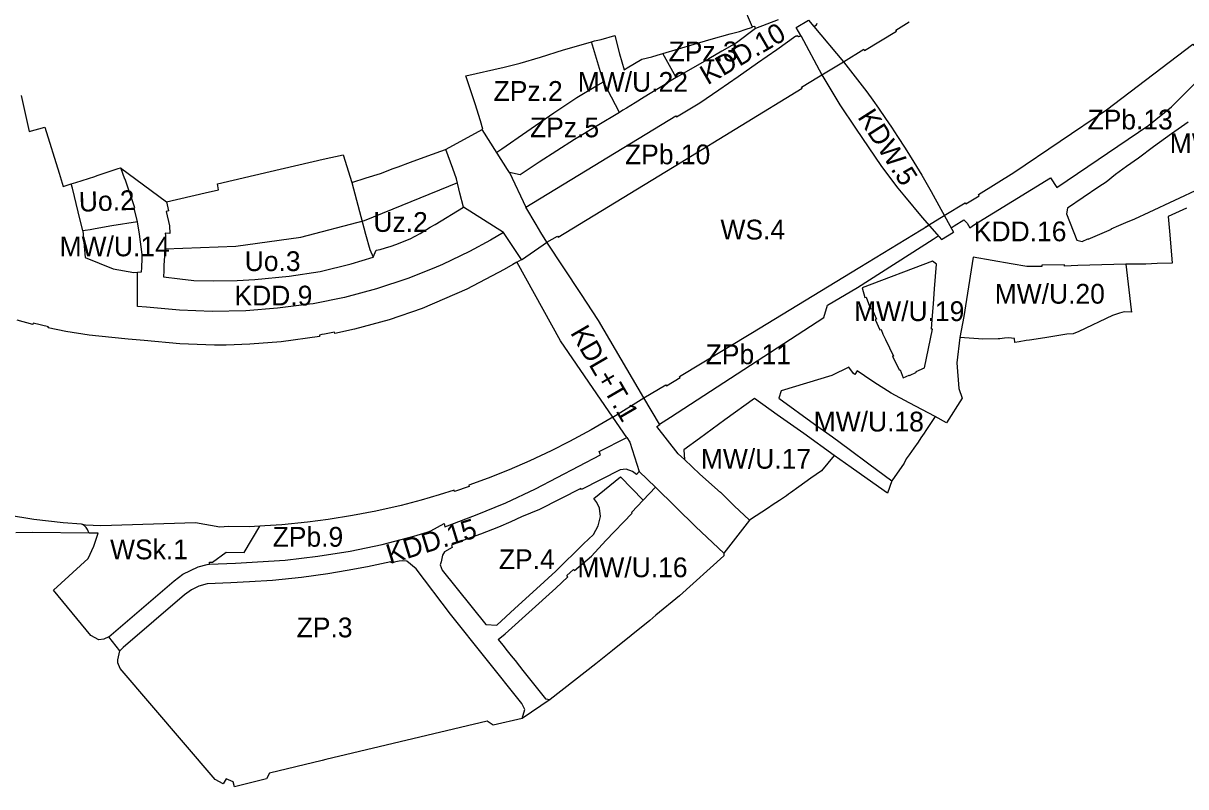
# Model space of a CAD drawing. Extents: x 7421697 to 7426767, y 5545731 to 5547485.
# Drawn here: x 7424103 to 7424808, y 5545731 to 5546195 of the extents above; entities that cross this region are included whole.
import ezdxf

# ---------------------------------------------------------------- set-up
doc = ezdxf.new("R2010")
doc.units = 0
for name, color, linetype in [('LIN_Linia Zabudowy Nieprzekraczalna', 7, 'Continuous'), ('LIN_linie rozgraniczające terenu WS', 7, 'Continuous'), ('LIN_linie_rozgraniczajace', 7, 'Continuous'), ('TXT_oznaczenia_przeznaczen', 7, 'Continuous')]:
    doc.layers.add(name, color=color, linetype=linetype)

msp = doc.modelspace()

# ---------------------------------------------------------------- linework, layer by layer
at = {"layer": 'LIN_Linia Zabudowy Nieprzekraczalna'}
msp.add_lwpolyline([(7424188.67, 5546057.57), (7424231.56, 5546059.31), (7424271.15, 5546064.63), (7424309.6, 5546074.83), (7424366.27, 5546097.92)], dxfattribs=at)
at = {"layer": 'LIN_linie rozgraniczające terenu WS'}
for p, q in [((7424587.09, 5546163.3), (7424600.39, 5546171.17)), ((7424649.85, 5546070.74), (7424663.46, 5546079.04)), ((7424404.94, 5546051.05), (7424420.79, 5546061.97)), ((7424460.37, 5545955.49), (7424479.27, 5545967.2))]:
    msp.add_line(p, q, dxfattribs=at)
at = {"layer": 'LIN_linie_rozgraniczajace'}
for p, q in [((7424613.11, 5546178.03), (7424632.48, 5546189.8)), ((7424632.03, 5546190.43), (7424640.26, 5546195.44)), ((7424632.48, 5546189.8), (7424632.03, 5546190.43)), ((7424600.39, 5546171.17), (7424612.71, 5546178.75)), ((7424612.71, 5546178.75), (7424613.11, 5546178.03)), ((7424574.84, 5546155.74), (7424585.09, 5546162.09)), ((7424585.09, 5546162.09), (7424587.09, 5546163.3)), ((7424427.2, 5546064.7), (7424501.23, 5546109.89)), ((7424420.39, 5546061.74), (7424426.78, 5546065.34)), ((7424426.78, 5546065.34), (7424427.2, 5546064.7)), ((7424503.4, 5545935.69), (7424503.87, 5545929.68))]:
    msp.add_line(p, q, dxfattribs=at)
for points in [[(7424661.5, 5546077.85), (7424674.13, 5546085.55), (7424674.6, 5546084.85), (7424682.6, 5546089.82), (7424682.16, 5546090.62), (7424703.77, 5546103.94), (7424759.9, 5546141.92), (7424812.22, 5546181.85), (7424812.78, 5546181.29), (7424819.99, 5546187.21), (7424819.56, 5546187.81), (7424862.07, 5546222.28), (7424940.6, 5546285.37), (7424941.01, 5546284.88), (7424947.89, 5546290.38), (7424947.41, 5546291.07), (7424989.15, 5546324.66), (7425042.17, 5546367.38), (7425042.68, 5546366.91), (7425050.01, 5546372.94), (7425049.68, 5546373.37), (7425057.27, 5546379.65)], [(7424726.02, 5546100.65), (7424729.7, 5546094.76), (7424785.69, 5546132.59), (7424799.27, 5546143.76), (7424814.44, 5546158.92), (7424817.02, 5546156.64), (7424824.01, 5546164.62), (7424825.31, 5546163.3), (7424847.73, 5546174.18), (7424880.46, 5546189.25), (7424887.59, 5546192.02), (7424920.27, 5546204.59), (7424932.07, 5546209.24), (7424938.37, 5546211.81), (7424940.05, 5546212.41), (7424965.34, 5546222.37)], [(7424101.33, 5546150.7), (7424106.15, 5546128.94), (7424115.62, 5546131.45), (7424124.43, 5546103.47), (7424126.76, 5546095.42), (7424131.78, 5546097.02), (7424134.43, 5546097.87), (7424146.06, 5546101.58), (7424147.53, 5546102.08), (7424160.13, 5546106.33), (7424161.71, 5546106.86), (7424189.62, 5546086.1), (7424212.98, 5546091.55), (7424221.18, 5546093.49), (7424220.42, 5546097.17), (7424252.51, 5546104.62), (7424284.6, 5546112.07), (7424296.8, 5546114.75), (7424301.95, 5546097.81), (7424310.65, 5546100.63), (7424319.35, 5546103.44), (7424327.17, 5546106.31), (7424330.13, 5546107.4), (7424337.57, 5546110.13), (7424348.21, 5546113.98), (7424358.85, 5546117.82), (7424381.51, 5546130.31), (7424380.05, 5546135.25), (7424376.88, 5546145.57), (7424371.09, 5546162.62), (7424394.47, 5546167.81), (7424404.05, 5546170.39), (7424416.4, 5546174.05), (7424430.44, 5546178.37), (7424435.59, 5546179.86), (7424447.5, 5546183.3), (7424449.33, 5546183.82), (7424453.36, 5546184.73), (7424461.49, 5546187.01), (7424464.34, 5546175.96), (7424467.22, 5546166.19), (7424469.05, 5546167.46), (7424477.89, 5546172.7), (7424484.1, 5546174.23), (7424487.3, 5546175.18), (7424490.61, 5546176.16), (7424509.81, 5546181.88), (7424520.1, 5546184.81), (7424531.63, 5546188.05), (7424537.19, 5546189.56), (7424540.62, 5546190.71), (7424545.19, 5546192.12), (7424539.23, 5546206)], [(7424560.75, 5546196.68), (7424546.86, 5546191.31), (7424535.36, 5546182.66), (7424526.55, 5546177.69), (7424518.53, 5546173.04), (7424510.5, 5546168.38), (7424498.82, 5546161.61), (7424498.72, 5546161.55), (7424495.69, 5546159.85), (7424495.77, 5546159.71), (7424492.03, 5546157.43), (7424492.09, 5546157.32), (7424483, 5546151.84), (7424482.93, 5546151.95), (7424479.38, 5546149.76), (7424473.98, 5546146.34), (7424468.58, 5546142.93), (7424466.49, 5546141.69), (7424464.4, 5546140.44), (7424450.77, 5546132.22), (7424437.14, 5546124.01), (7424415.75, 5546110.28), (7424404.24, 5546102.58), (7424397.72, 5546103.87), (7424407.56, 5546082.85), (7424453.09, 5546110.59), (7424498.62, 5546138.32), (7424498.99, 5546137.75), (7424513.17, 5546146.25), (7424524.76, 5546154.15), (7424536.49, 5546162.32), (7424548.23, 5546170.49), (7424548.23, 5546170.49), (7424559.8, 5546178.7), (7424571.38, 5546186.91), (7424571.64, 5546186.52), (7424572.26, 5546187.02), (7424573.11, 5546186.47), (7424573.79, 5546186.66), (7424574.46, 5546187.12), (7424571.69, 5546192.01), (7424579.06, 5546196.33), (7424582.31, 5546192.49), (7424583.87, 5546193.55), (7424584.26, 5546194.6)], [(7424546.86, 5546191.31), (7424546.44, 5546192.52), (7424545.11, 5546192.32)], [(7424582.31, 5546192.49), (7424600.39, 5546171.17), (7424614.59, 5546152.9), (7424618.11, 5546147.95), (7424621.55, 5546142.92), (7424625.89, 5546136.74), (7424629.48, 5546131.46), (7424633.14, 5546125.85), (7424637.71, 5546118.81), (7424642.99, 5546110.25), (7424647.79, 5546102.29), (7424653.46, 5546092.47), (7424659.42, 5546081.63), (7424667.08, 5546067.7)], [(7424464.4, 5546140.44), (7424454.67, 5546158.92), (7424447.5, 5546183.3)], [(7424574.46, 5546187.12), (7424587.09, 5546163.3), (7424598.19, 5546145.08), (7424607.56, 5546130.84), (7424623.42, 5546107.69), (7424633.38, 5546094.51), (7424637.32, 5546089.56), (7424648.09, 5546076.64), (7424656.96, 5546066.46), (7424659.87, 5546063.33)], [(7424498.82, 5546161.61), (7424490.61, 5546176.16)], [(7424389.92, 5546116.2), (7424393.09, 5546118.28), (7424408.21, 5546128.87), (7424424.64, 5546140.14), (7424438.61, 5546149.43), (7424450.1, 5546156.27), (7424454.67, 5546158.92)], [(7424501.23, 5546109.89), (7424575.26, 5546155.09), (7424574.84, 5546155.74)], [(7424809.47, 5546134.53), (7424799.3, 5546127.52), (7424788.51, 5546119.6), (7424779.38, 5546112.7), (7424772.1, 5546107.6), (7424765.39, 5546102.68), (7424759.79, 5546098.14), (7424755.32, 5546095.28), (7424736.16, 5546082.26), (7424735.65, 5546078.9), (7424741.94, 5546062.85), (7424745.12, 5546062.06), (7424748.6, 5546063.68), (7424748.73, 5546063.49), (7424762.88, 5546069.6), (7424762.83, 5546069.75), (7424767.43, 5546071.74), (7424771.6, 5546073.58), (7424777.19, 5546075.87), (7424785.77, 5546079.88), (7424848.07, 5546108.93)], [(7424397.72, 5546103.87), (7424396.53, 5546105.75), (7424390.18, 5546115.79), (7424381.06, 5546130.06)], [(7424468.81, 5545943.17), (7424460.37, 5545955.49), (7424428.66, 5546001.79), (7424402.32, 5546049.26), (7424402.17, 5546049.54), (7424404.88, 5546051.15), (7424394, 5546067.56), (7424369.71, 5546082.87), (7424367.58, 5546091.46), (7424365.46, 5546100.04), (7424363.2, 5546106.38), (7424359.08, 5546117.95)], [(7424394, 5546067.56), (7424386.24, 5546062.84), (7424373.35, 5546056.1), (7424357.02, 5546048.04), (7424351.81, 5546045.86), (7424335.93, 5546039.66), (7424316.96, 5546033.33), (7424297.54, 5546028.08), (7424278.49, 5546024.28), (7424276.32, 5546024), (7424256.98, 5546021.52), (7424237.75, 5546020.04), (7424217.21, 5546019.67), (7424197.37, 5546020.37), (7424177.35, 5546022.14), (7424171.91, 5546022.67), (7424171.93, 5546042.54), (7424171.92, 5546043.55), (7424174.4, 5546043.76), (7424174.55, 5546046.09), (7424174.56, 5546047.23), (7424174.7, 5546050.73), (7424174.84, 5546054.23), (7424173.25, 5546066.49), (7424172.02, 5546074.08), (7424170, 5546082.34), (7424170.25, 5546082.45), (7424164.51, 5546099.97), (7424164.26, 5546099.88), (7424161.88, 5546106.74)], [(7424665.61, 5546070.39), (7424667.5, 5546071.6), (7424673.41, 5546075.17), (7424675.34, 5546073.12), (7424676.95, 5546070.29), (7424679.88, 5546072.3), (7424726.02, 5546100.65)], [(7424172.02, 5546074.08), (7424156.37, 5546071.53), (7424146.32, 5546069.79), (7424143.24, 5546069.25), (7424140.16, 5546068.72), (7424138.85, 5546068.51), (7424136, 5546080.17), (7424132.43, 5546094.42), (7424131.78, 5546097.02)], [(7424301.95, 5546097.81), (7424310.36, 5546066.43), (7424312.93, 5546057.28), (7424314.86, 5546052.51)], [(7424189.62, 5546086.1), (7424190.68, 5546080.72), (7424189.3, 5546080.37), (7424191.35, 5546071.66), (7424191.63, 5546066.96), (7424188.82, 5546067.06), (7424188.88, 5546065.7), (7424188.69, 5546062.56), (7424188.5, 5546059.41), (7424188.26, 5546053.44), (7424188.02, 5546047.47), (7424187.84, 5546044.33), (7424187.72, 5546040.61), (7424197.71, 5546039.33), (7424206.07, 5546038.49), (7424218.09, 5546038.15), (7424232.44, 5546038.36), (7424243.16, 5546038.93), (7424263.92, 5546041.02), (7424282.78, 5546043.97), (7424301.52, 5546048.45), (7424314.86, 5546052.51), (7424316.69, 5546056.73), (7424319.14, 5546057.28), (7424322.35, 5546058.15), (7424325.95, 5546059.24), (7424328.75, 5546060.25), (7424337.33, 5546063.71), (7424343.56, 5546066.98), (7424349.63, 5546070.71), (7424352.64, 5546072.47), (7424369.71, 5546082.87)], [(7424808.45, 5546082.3), (7424797.36, 5546077.18), (7424798.26, 5546066.2), (7424799.84, 5546048.89), (7424790.61, 5546048.75), (7424783.79, 5546048.22), (7424771.74, 5546048.37), (7424774.95, 5546020.68), (7424775.08, 5546019.1), (7424770.7, 5546019.31), (7424767.88, 5546018.68), (7424763.65, 5546017.25), (7424743.21, 5546007.47), (7424739.64, 5546006.03), (7424735.8, 5546005.93), (7424729.77, 5546004.85), (7424727.38, 5546004.42), (7424722.6, 5546003.69), (7424713.15, 5546002.25), (7424711.09, 5546001.94), (7424706.97, 5546001.14), (7424704.31, 5546000.74), (7424704.08, 5546003.26), (7424700.39, 5546003.6), (7424698.07, 5546003.35), (7424695.16, 5546003.06), (7424694.13, 5546002.94), (7424684.64, 5546002.85), (7424682.18, 5546003), (7424670.83, 5546003.74), (7424669.2, 5545988.43), (7424670.36, 5545972.81), (7424672.29, 5545966.97), (7424662.89, 5545952.08), (7424655.9, 5545955.88), (7424650.34, 5545947.38), (7424649.26, 5545945.79), (7424647.32, 5545942.84), (7424645.64, 5545940.29), (7424642.98, 5545936.57), (7424640.17, 5545932.63), (7424638.45, 5545930.2), (7424637.11, 5545927.45), (7424629.71, 5545916.81), (7424627.04, 5545909.31), (7424614.75, 5545918.04), (7424605.07, 5545924.98), (7424594.64, 5545932.29), (7424586.92, 5545922.86), (7424580.61, 5545918.49), (7424573.29, 5545913.23), (7424568.1, 5545909.49), (7424567.04, 5545908.71), (7424565.78, 5545907.77), (7424561.48, 5545904.79), (7424557.01, 5545902.06), (7424554.74, 5545900.52), (7424543.33, 5545892.87), (7424527.77, 5545872.97), (7424527.75, 5545871.27), (7424500.88, 5545847.03), (7424486.55, 5545835.35), (7424482.89, 5545832.08), (7424460.15, 5545813.92), (7424450.03, 5545805.7), (7424437.19, 5545795.66), (7424422.38, 5545784.09), (7424405.27, 5545772.63), (7424387.67, 5545768.43), (7424384.02, 5545770.97), (7424286.2, 5545747.59), (7424283.97, 5545747.07), (7424252.14, 5545739.42), (7424250.25, 5545736.03), (7424230.71, 5545731.14), (7424229.96, 5545734.09), (7424225.84, 5545736), (7424223.94, 5545732.91), (7424219.03, 5545735.62), (7424161.47, 5545802.94), (7424159.98, 5545806.34), (7424160.04, 5545808.19), (7424161.26, 5545813.57), (7424154.51, 5545822.14), (7424151.49, 5545820.74), (7424148.46, 5545820.35), (7424143.59, 5545822.91), (7424120.89, 5545850.41), (7424141.94, 5545869.64), (7424145.35, 5545877.24), (7424148.1, 5545884.97), (7424142.71, 5545885.03), (7424108.1, 5545885.42), (7424098.05, 5545885.35)], [(7424543.33, 5545892.87), (7424534.06, 5545901.69), (7424525.72, 5545909.88), (7424525.61, 5545909.77), (7424513.26, 5545920.85), (7424503.87, 5545929.68), (7424500.06, 5545933.27), (7424487.02, 5545949.72), (7424488.87, 5545950.94), (7424488.69, 5545951.24), (7424479.27, 5545967.2), (7424451.6, 5546014.05), (7424440.96, 5546030.46), (7424420.39, 5546061.74), (7424416.7, 5546067.64), (7424413.86, 5546072.38), (7424407.56, 5546082.85)], [(7424479.27, 5545967.2), (7424492.56, 5545975.03), (7424492.98, 5545974.46), (7424501.13, 5545979.5), (7424500.74, 5545980.18), (7424544.18, 5546006.26), (7424610.18, 5546046.57), (7424652.05, 5546072.09)], [(7424138.85, 5546068.51), (7424140.28, 5546052.41), (7424157.13, 5546045.42), (7424169.69, 5546043.36), (7424171.92, 5546043.55)], [(7424488.69, 5545951.24), (7424495.31, 5545955.42), (7424588.36, 5546015.9), (7424590.67, 5546023.47), (7424608.83, 5546034.23), (7424654.75, 5546063.47)], [(7424654.75, 5546063.47), (7424657.88, 5546065.47)], [(7424659.87, 5546063.33), (7424667.08, 5546067.7)], [(7424402.17, 5546049.54), (7424399.7, 5546048.07), (7424394.52, 5546045), (7424371.75, 5546033.08), (7424371.75, 5546033.08), (7424358.21, 5546027.28), (7424344.67, 5546021.47), (7424324.6, 5546014.59), (7424303.65, 5546008.86), (7424291.76, 5546006.2), (7424291.58, 5546007.05), (7424288.49, 5546006.46), (7424285.39, 5546005.88), (7424283.87, 5546005.58), (7424282.35, 5546005.29), (7424282.46, 5546004.47), (7424259.03, 5546001.16), (7424240.06, 5545999.68), (7424225.75, 5545999.2), (7424218.75, 5545999.22), (7424197.59, 5546000.04), (7424176.04, 5546001.89), (7424166.25, 5546002.82), (7424156.46, 5546003.74), (7424142.59, 5546005.26), (7424128.45, 5546007.47), (7424117.7, 5546009.58), (7424117.87, 5546010.38), (7424108.67, 5546012.49), (7424108.51, 5546011.67), (7424098.91, 5546014.37)], [(7424656.76, 5546048.32), (7424654.31, 5546050.13), (7424611.6, 5546033.97)], [(7424771.74, 5546048.37), (7424742.43, 5546047.45), (7424734.42, 5546047.18), (7424734.49, 5546047.85), (7424720.68, 5546047.62), (7424720.68, 5546046.98), (7424711.56, 5546046.85), (7424702.05, 5546048.56), (7424679.01, 5546052.66), (7424674.92, 5546026.78), (7424673.28, 5546016.49), (7424670.83, 5546003.74)], [(7424611.6, 5546033.97), (7424613.32, 5546028.17), (7424614.01, 5546028.29), (7424616.74, 5546021.18), (7424617.51, 5546021.4), (7424620.35, 5546015.02), (7424619.62, 5546014.66), (7424622.47, 5546008.48), (7424623.14, 5546008.63), (7424624.3, 5546005.8), (7424625.79, 5546002.63), (7424630.59, 5545992.57), (7424630.04, 5545992.52), (7424634.16, 5545984.15), (7424634.76, 5545984.22), (7424636.61, 5545979.33), (7424640.25, 5545981.03), (7424640.45, 5545980.73), (7424644.6, 5545982.8), (7424644.47, 5545983.08), (7424649.52, 5545985.48), (7424654.38, 5546008.88), (7424653.77, 5546008.83), (7424654.23, 5546014.78), (7424654.89, 5546024.34), (7424655.46, 5546033.45), (7424656.76, 5546048.32)], [(7424655.9, 5545955.88), (7424640.24, 5545964.19), (7424629.35, 5545969.97), (7424618.76, 5545976.7), (7424613.14, 5545980.49), (7424608.63, 5545983.52), (7424607.14, 5545981.37), (7424606.32, 5545981.93), (7424603.53, 5545985.87), (7424593.18, 5545980.66), (7424562.61, 5545971.41), (7424561.06, 5545966.94), (7424582.82, 5545951.27), (7424593.7, 5545943.45), (7424603.69, 5545936), (7424615.68, 5545927.14), (7424629.71, 5545916.81)], [(7424594.64, 5545932.29), (7424576.25, 5545945.5), (7424560.01, 5545956.92), (7424546.24, 5545966.81), (7424528.35, 5545953.82), (7424512.87, 5545942.58), (7424503.4, 5545935.69)], [(7424460.37, 5545955.49), (7424459.45, 5545954.93), (7424447.25, 5545947.74), (7424434.12, 5545940.6), (7424422.92, 5545934.93), (7424410.02, 5545928.87), (7424397.52, 5545923.49), (7424384.69, 5545918.42), (7424373.03, 5545914.17), (7424373.29, 5545913.38), (7424364.29, 5545910.3), (7424364.03, 5545911.13), (7424354.94, 5545908.27), (7424344.08, 5545905.12), (7424331.92, 5545901.94), (7424316.59, 5545898.41), (7424302.5, 5545895.71), (7424287.65, 5545893.33), (7424275.17, 5545891.68), (7424259.54, 5545890.17), (7424249.23, 5545889.47), (7424246.17, 5545889.26), (7424239.63, 5545888.81), (7424227.08, 5545889.06), (7424221.85, 5545888.66), (7424207.08, 5545891.34), (7424149.74, 5545889.42), (7424140.44, 5545889.85), (7424138.63, 5545890.31), (7424137.95, 5545890.48), (7424126.85, 5545891.29), (7424109.13, 5545893.25), (7424093.15, 5545896.05)], [(7424154.51, 5545822.14), (7424194.18, 5545856.12), (7424199.39, 5545860.08), (7424204.04, 5545862.41), (7424208.75, 5545864.65), (7424214.15, 5545866.1), (7424215.55, 5545866.17), (7424231.44, 5545866.89), (7424261.59, 5545868.72), (7424281.41, 5545871.06), (7424300.95, 5545874.22), (7424320.45, 5545878.18), (7424339.61, 5545883.26), (7424347.81, 5545885.64), (7424349.93, 5545886.53), (7424357.99, 5545890.99), (7424358.52, 5545888.83), (7424377.1, 5545895.95), (7424395.39, 5545903.51), (7424413.41, 5545912.01), (7424452.95, 5545932.68), (7424451.99, 5545934.62), (7424468.81, 5545943.17), (7424470.62, 5545940.29), (7424476.33, 5545922.56), (7424474.73, 5545920.71), (7424472.26, 5545922.4), (7424468.52, 5545923.98), (7424464.83, 5545923.46), (7424441.33, 5545911.6), (7424441, 5545912.2), (7424415.84, 5545899.39), (7424405, 5545894.9), (7424398.41, 5545891.95), (7424390.99, 5545888.61), (7424380.16, 5545884.54), (7424370.97, 5545881.14), (7424362.52, 5545877.87), (7424362.97, 5545876.3), (7424358.32, 5545873.75), (7424357.07, 5545871.74), (7424356.28, 5545867.72), (7424355.53, 5545865.86), (7424356.88, 5545862.64), (7424383.38, 5545829.67)], [(7424527.77, 5545872.97), (7424510.81, 5545888.99), (7424486.21, 5545912.94), (7424476.33, 5545922.56)], [(7424383.38, 5545829.67), (7424389.97, 5545829.12), (7424400.97, 5545839.23), (7424414.05, 5545851.29), (7424425.86, 5545862.08), (7424442.62, 5545878.68), (7424448.6, 5545884.33), (7424451.46, 5545889.49), (7424452.94, 5545895.13), (7424452.38, 5545900.17), (7424450.72, 5545903.72), (7424448.87, 5545906.19), (7424464.93, 5545919.32), (7424478.81, 5545905.08)], [(7424390.74, 5545820.5), (7424395.07, 5545823.99), (7424425.8, 5545851.62), (7424432.97, 5545858.59), (7424432.36, 5545859.26), (7424436.48, 5545863.02), (7424437.08, 5545862.35), (7424447.4, 5545871.15), (7424456.1, 5545880.59), (7424472.07, 5545897.2), (7424471.73, 5545897.56), (7424478.81, 5545905.08), (7424486.21, 5545912.94)], [(7424142.71, 5545885.03), (7424142.08, 5545886.25), (7424141.55, 5545887.26), (7424140.74, 5545888.48), (7424139.71, 5545889.53), (7424138.63, 5545890.31)], [(7424215.55, 5545866.17), (7424215.57, 5545867.48), (7424217.41, 5545867.55), (7424225.72, 5545873.44), (7424236.71, 5545873.37), (7424246.17, 5545889.26)], [(7424405.27, 5545772.63), (7424406.99, 5545778.12), (7424405.08, 5545781.65), (7424361.87, 5545835.95), (7424341.11, 5545863.35), (7424335.39, 5545867.99), (7424332.77, 5545868.24), (7424330.8, 5545867.98), (7424325.9, 5545866.95), (7424325.62, 5545867.58), (7424311.5, 5545864.7), (7424299.23, 5545862.44), (7424287.51, 5545860.4), (7424271.43, 5545858.19), (7424253.79, 5545856.36), (7424239.86, 5545855.59), (7424228.53, 5545854.97), (7424214.22, 5545854.23), (7424209.18, 5545852.98), (7424204.63, 5545850.6), (7424200.43, 5545847.68), (7424163.18, 5545815.58), (7424161.26, 5545813.57)], [(7424390.74, 5545820.5), (7424393.53, 5545817.07), (7424396.32, 5545813.64), (7424398.77, 5545810.58), (7424401.07, 5545807.71), (7424403.71, 5545804.41), (7424405.85, 5545801.76), (7424419.56, 5545784.49), (7424422.38, 5545784.09)]]:
    msp.add_lwpolyline(points, dxfattribs=at)

# ---------------------------------------------------------------- texts
at = {"layer": 'TXT_oznaczenia_przeznaczen'}
for s, rotation, p in [('KDD.10', 30.25198, (7424517.83, 5546156.81)), ('KDW.5', 302.57419, (7424608.55, 5546137.61)), ('Uo.2', 1.96361, (7424136.52, 5546080.12)), ('KDL+T.1', 300.16887, (7424434.31, 5546006.71)), ('KDD.15', 17.11104, (7424325.09, 5545866.21))]:
    msp.add_text(s, height=12, rotation=rotation, dxfattribs=at).set_placement(p)
for s, p in [('ZPz.3', (7424494.23, 5546171.46)), ('MW/U.22', (7424439.09, 5546152.95)), ('ZPz.2', (7424388.05, 5546147.44)), ('ZPb.13', (7424748.42, 5546130.07)), ('ZPz.5', (7424410.13, 5546125.33)), ('MW/U.21', (7424798.29, 5546115.75)), ('ZPb.10', (7424467.76, 5546108.94)), ('Uz.2', (7424315.08, 5546067.91)), ('WS.4', (7424525.69, 5546063.3)), ('KDD.16', (7424679.44, 5546062.21)), ('MW/U.14', (7424124.64, 5546053.11)), ('Uo.3', (7424236.99, 5546044.13)), ('KDD.9', (7424230.81, 5546023.25)), ('MW/U.20', (7424692.07, 5546024.35)), ('MW/U.19', (7424606.81, 5546013.79)), ('ZPb.11', (7424516.72, 5545987.61)), ('MW/U.18', (7424582.23, 5545946.76)), ('MW/U.17', (7424513.79, 5545924.17)), ('ZPb.9', (7424253.96, 5545876.82)), ('WSk.1', (7424155.3, 5545869.19)), ('ZP.4', (7424391.21, 5545863.23)), ('MW/U.16', (7424438.84, 5545858.31)), ('ZP.3', (7424268.52, 5545821.84))]:
    msp.add_text(s, height=12, dxfattribs=at).set_placement(p)

doc.saveas('drawing.dxf')
